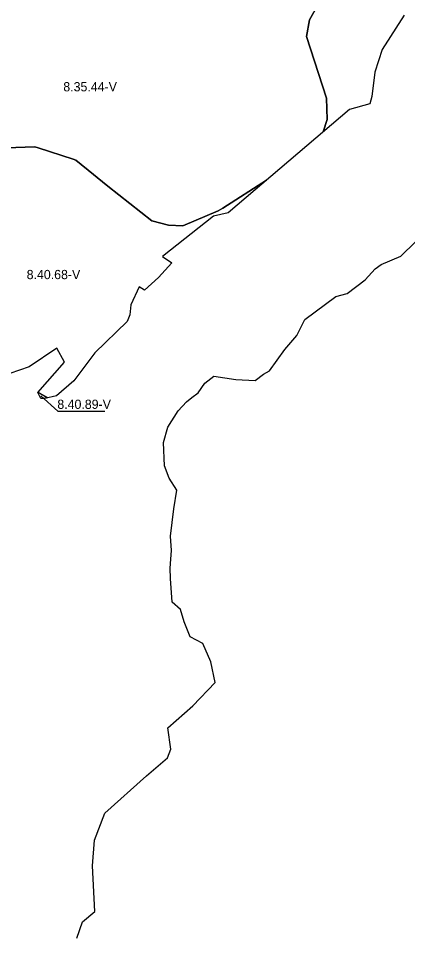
# Model space of a CAD drawing. Extents: x -547623 to -533936, y -1096714 to -1086523.
# Drawn here: x -543971 to -543550, y -1095788 to -1094794 of the extents above; entities that cross this region are included whole.
import ezdxf

# ---------------------------------------------------------------- set-up
doc = ezdxf.new("R2010")
doc.units = 0
doc.layers.add('Vrstva 27', color=7, linetype='Continuous')
doc.layers.add('Vrstva 28', color=7, linetype='Continuous')

msp = doc.modelspace()

# ---------------------------------------------------------------- linework, layer by layer
at = {"layer": 'Vrstva 27'}
msp.add_lwpolyline([(-543946.72, -1095202.46), (-543928.65, -1095219.05), (-543877.64, -1095219.05)], dxfattribs=at)
at = {"layer": 'Vrstva 28'}
for p, q in [((-543648.5, -1094781.5), (-543656.5, -1094795.5)), ((-543656.5, -1094795.5), (-543648.5, -1094781.5)), ((-543656.5, -1094795.5), (-543659.5, -1094813.5)), ((-543659.5, -1094813.5), (-543656.5, -1094795.5)), ((-543659.5, -1094813.5), (-543638, -1094880.5)), ((-543638, -1094880.5), (-543659.5, -1094813.5)), ((-543638, -1094880.5), (-543637.5, -1094903.5)), ((-543637.5, -1094903.5), (-543638, -1094880.5)), ((-543637.5, -1094903.5), (-543641.63, -1094916.85)), ((-543641.63, -1094916.85), (-543637.5, -1094903.5)), ((-543641.63, -1094916.85), (-543641.63, -1094916.85)), ((-543641.63, -1094916.85), (-543641.63, -1094916.85)), ((-543953.5, -1094933), (-543984.5, -1094934)), ((-543984.5, -1094934), (-543953.5, -1094933)), ((-543949.72, -1094934.23), (-543953.5, -1094933)), ((-543953.5, -1094933), (-543949.72, -1094934.23)), ((-543912.01, -1094946.52), (-543949.72, -1094934.23)), ((-543949.72, -1094934.23), (-543912.01, -1094946.52)), ((-543909, -1094947.5), (-543912.01, -1094946.52)), ((-543912.01, -1094946.52), (-543909, -1094947.5)), ((-543889.95, -1094962.96), (-543909, -1094947.5)), ((-543909, -1094947.5), (-543889.95, -1094962.96)), ((-543886.11, -1094966.08), (-543889.95, -1094962.96)), ((-543889.95, -1094962.96), (-543886.11, -1094966.08)), ((-543874.5, -1094975.5), (-543886.11, -1094966.08)), ((-543886.11, -1094966.08), (-543874.5, -1094975.5)), ((-543702.99, -1094969.06), (-543750, -1094999.28)), ((-543750, -1094999.28), (-543702.99, -1094969.06)), ((-543827, -1095013), (-543874.5, -1094975.5)), ((-543874.5, -1094975.5), (-543827, -1095013)), ((-543755, -1095002.5), (-543793.5, -1095018.5)), ((-543793.5, -1095018.5), (-543755, -1095002.5)), ((-543750, -1094999.28), (-543755, -1095002.5)), ((-543755, -1095002.5), (-543750, -1094999.28)), ((-543809, -1095018), (-543827, -1095013)), ((-543827, -1095013), (-543809, -1095018)), ((-543793.5, -1095018.5), (-543809, -1095018)), ((-543809, -1095018), (-543793.5, -1095018.5)), ((-543949.74, -1095198.64), (-543942, -1095203.5)), ((-543940.02, -1095204.77), (-543942, -1095203.5)), ((-543942, -1095203.5), (-543940.02, -1095204.77))]:
    msp.add_line(p, q, dxfattribs=at)
for points in [[(-543641.63, -1094916.85), (-543641.63, -1094916.85), (-543637.5, -1094903.5), (-543638, -1094880.5), (-543659.5, -1094813.5), (-543656.5, -1094795.5), (-543648.5, -1094781.5)], [(-543554.15, -1094790.67), (-543577.79, -1094827.76), (-543585.69, -1094852.38), (-543589.11, -1094878.41), (-543591.14, -1094886.44), (-543613.04, -1094892.52), (-543744.43, -1095004.33), (-543760.11, -1095008.17), (-543815.42, -1095051.86), (-543805.36, -1095058.69), (-543819.56, -1095074.39), (-543834.78, -1095088.11), (-543840.58, -1095084.63), (-543849.46, -1095104.16), (-543850.83, -1095114.91), (-543853.51, -1095122.24), (-543888.38, -1095156.12), (-543911.35, -1095186.48), (-543929.95, -1095202.65), (-543942.63, -1095205.32), (-543943.57, -1095205.35), (-543947.07, -1095205.47), (-543950.15, -1095199.1), (-543921.18, -1095166.28), (-543929.46, -1095151), (-543959.39, -1095171.25), (-544001.62, -1095185.56)], [(-543984.5, -1094934), (-543953.5, -1094933), (-543949.72, -1094934.23), (-543912.01, -1094946.52), (-543909, -1094947.5), (-543889.95, -1094962.96), (-543886.11, -1094966.08), (-543874.5, -1094975.5), (-543827, -1095013), (-543809, -1095018), (-543793.5, -1095018.5), (-543755, -1095002.5), (-543750, -1094999.28), (-543702.99, -1094969.06)], [(-543907.92, -1095789.75), (-543901.68, -1095771.97), (-543888.38, -1095760.9), (-543890.88, -1095711.27), (-543888.78, -1095683.47), (-543877.87, -1095654.44), (-543832.7, -1095613.93), (-543810.04, -1095594.32), (-543806.49, -1095585.04), (-543809.66, -1095562.01), (-543782.52, -1095538.13), (-543758.34, -1095512.83), (-543763.16, -1095490.46), (-543771.88, -1095470.67), (-543785.39, -1095463.33), (-543791.96, -1095447.35), (-543795.89, -1095433.91), (-543804.91, -1095425.81), (-543806.78, -1095400.33), (-543807.14, -1095389.12), (-543806.46, -1095379.54), (-543805.52, -1095369.98), (-543806.74, -1095354.33), (-543803.26, -1095324.95), (-543799.73, -1095304.79), (-543808.12, -1095291.87), (-543813.3, -1095278.24), (-543814.19, -1095253.19), (-543809.69, -1095236.43), (-543798.54, -1095218.8), (-543789.3, -1095208.99), (-543783.63, -1095204.33), (-543776.73, -1095199.21), (-543769.59, -1095188.94), (-543759.7, -1095181.3), (-543736.2, -1095184.93), (-543715.18, -1095186.06), (-543706.18, -1095179.16), (-543699.85, -1095175.39), (-543683.06, -1095152.46), (-543670.09, -1095137.4), (-543661.39, -1095120.01), (-543628.01, -1095095.25), (-543615.83, -1095091.83), (-543596.39, -1095076.96), (-543585.6, -1095065.3), (-543578.87, -1095060.6), (-543557.72, -1095051.31), (-543541.91, -1095035.81)]]:
    msp.add_lwpolyline(points, dxfattribs=at)

# ---------------------------------------------------------------- texts
at = {"layer": 'Vrstva 27'}
for s, p in [('8.35.44-V', (-543922.6, -1094873.02)), ('8.40.68-V', (-543962.22, -1095076.3)), ('8.40.89-V', (-543929.07, -1095216.74))]:
    msp.add_text(s, height=10, dxfattribs=at).set_placement(p)

doc.saveas('drawing.dxf')
